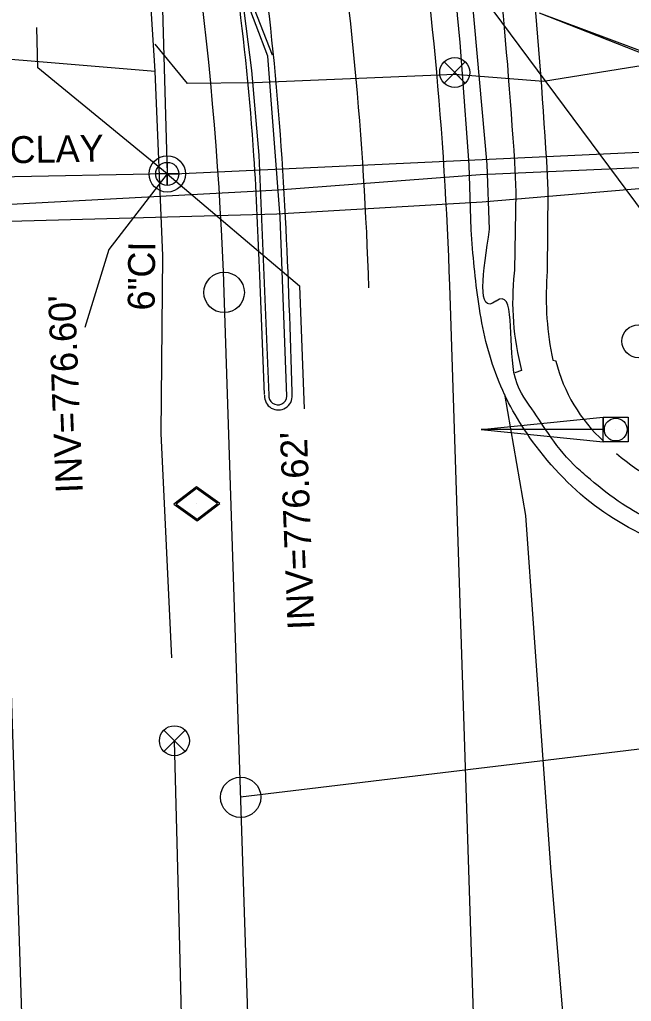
# Model space of a CAD drawing. Extents: x 1627482 to 1629573, y 760826 to 766301.
# Drawn here: x 1628458.5 to 1628549.3, y 761670.2 to 761816 of the extents above; entities that cross this region are included whole.
import ezdxf

# ---------------------------------------------------------------- set-up
doc = ezdxf.new("R2010")
doc.units = 0
for name, color, linetype in [('Exist Horizontal Alignment', 7, 'Continuous'), ('Exist Horizontal Alignment Point', 7, 'Continuous'), ('Exist Other Culture Fence Line', 7, 'Continuous'), ('Exist Right of Way Line', 7, 'Continuous'), ('Exist Roads Curbs', 7, 'Continuous'), ('Exist Roads EOP', 7, 'Continuous'), ('Exist Roads EOP Other', 7, 'Continuous'), ('Exist Roads EOT', 7, 'Continuous'), ('Exist Structure Minor Pipes RCP 18 Inch', 7, 'Continuous'), ('Exist Utilities Gas UG Line SUE LOS B', 7, 'Continuous'), ('Exist Utilities Gas Valve CELL', 7, 'Continuous'), ('Exist Utilities Other Pole Metal with Mast Arm CELL', 7, 'Continuous'), ('Exist Utilities Power Pole CELL', 7, 'Continuous'), ('Exist Utilities Sanitary Sewer Manhole CELL', 7, 'Continuous'), ('Exist Utilities Sanitary Sewer Manhole Leader', 7, 'Continuous'), ('Exist Utilities Sanitary Sewer UG Line', 7, 'Continuous'), ('Exist Utilities Sanitary Sewer UG Line Invert Elevation', 7, 'Continuous'), ('Exist Utilities Sanitary Sewer UG Line Leader', 7, 'Continuous'), ('Exist Utilities Sanitary Sewer UG Line Text', 7, 'Continuous'), ('Exist Utilities Water UG Line SUE', 7, 'Continuous'), ('Exist Utilities Water UG Line SUE LOS B', 7, 'Continuous'), ('Exist Utilities Water UG Line SUE Text', 7, 'Continuous'), ('Exist Utilities Water Valve CELL', 7, 'Continuous')]:
    doc.layers.add(name, color=color, linetype=linetype)

# ---------------------------------------------------------------- blocks, each defined once
blk = doc.blocks.new('EXIST UTILITIES WATER VALVE')
at = {"layer": 'Exist Utilities Water Valve CELL'}
blk.add_lwpolyline([(0.03150000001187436, 0.03150000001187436), (-0.031499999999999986, -0.03149999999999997), (0, 1.4210854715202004e-17), (0.03150000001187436, -0.03150000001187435), (-0.031499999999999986, 0.03150000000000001)], dxfattribs=at)
blk.add_circle((0, 0), 0.044547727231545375, dxfattribs=at)
blk = doc.blocks.new('EXIST UTILITIES GAS VALVE')
at = {"layer": 'Exist Utilities Gas Valve CELL'}
blk.add_line((0, 0), (0, 0), dxfattribs=at)
blk.add_lwpolyline([(0, 0.06825), (-0.05075, 0), (0, -0.06825), (0.05075, 0), (0, 0.06825)], dxfattribs=at)
blk.add_lwpolyline([(0.04576534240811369, 7.27595761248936e-18), (7.27595761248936e-18, 0.06154649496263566), (-0.04576534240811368, 0), (-7.27595761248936e-18, -0.06154649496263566)], close=True, dxfattribs=at)

msp = doc.modelspace()

# ---------------------------------------------------------------- linework, layer by layer
at = {"layer": 'Exist Horizontal Alignment'}
for p, q in [((1628498.6647146, 761475.6274153), (1628488.856999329, 761775.4670536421)), ((1628626.1058687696, 761716.7643783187), (1628491.3084665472, 761700.5212559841))]:
    msp.add_line(p, q, dxfattribs=at)
msp.add_arc((1627989.1242687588, 761759.1208615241), 500, 1.8734694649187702, 13.294655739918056, dxfattribs=at)
at = {"layer": 'Exist Horizontal Alignment Point'}
for centre in [(1628488.856999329, 761775.4670536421), (1628491.3084665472, 761700.5212559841)]:
    msp.add_circle(centre, 3, dxfattribs=at)
at = {"layer": 'Exist Other Culture Fence Line'}
msp.add_lwpolyline([(1629023.0696787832, 761658.0081255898), (1628929.497, 761723.8569999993), (1628897.894, 761738.8069999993), (1628861.8800000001, 761754.8679999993), (1628824.045, 761767.8569999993), (1628781.593, 761778.1989999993), (1628741.5960000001, 761784.8469999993), (1628702.129, 761788.6019999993), (1628662.165, 761788.6189999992), (1628626.173, 761786.1319999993), (1628617.683, 761785.6939999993), (1628593.545, 761794.1689999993), (1628535.6424837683, 761816.9022530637)], dxfattribs=at)
at = {"layer": 'Exist Right of Way Line'}
msp.add_line((1628617.731430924, 761786.2616357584), (1628535.6424837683, 761816.9022530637), dxfattribs=at)
at = {"layer": 'Exist Roads Curbs'}
for p, q in [((1628527.894, 761794.4743), (1628525.279, 761823.6529)), ((1628528.2550000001, 761784.8776), (1628527.894, 761794.4743)), ((1628538.083, 761765.3112000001), (1628538.099, 761765.263)), ((1628545.188, 761753.3518), (1628545.27, 761753.2674)), ((1628547.0790000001, 761751.5445), (1628547.0860000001, 761751.5432))]:
    msp.add_line(p, q, dxfattribs=at)
for centre, major_axis, ratio, start_param, end_param in [((1628561.380740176, 761771.0624674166), (6.980355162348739, -22.97217452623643), 0.9993276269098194, 4.661558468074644, 5.247238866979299), ((1628571.504853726, 761780.4198696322), (-6.690798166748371, -37.221658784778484), 0.9998936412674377, 5.759046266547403, 6.144520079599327)]:
    msp.add_ellipse(centre, major_axis=major_axis, ratio=ratio, start_param=start_param, end_param=end_param, dxfattribs=at)
msp.add_spline([(1628585.152, 761739.0867), (1628570.641, 761737.1304), (1628557.995, 761739.2484000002), (1628552.564, 761741.491), (1628547.941, 761744.0812), (1628543.216, 761747.6779), (1628541.249, 761749.403), (1628537.348, 761753.9899000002), (1628534.545, 761758.167), (1628531.877, 761763.5616), (1628529.214, 761774.1799), (1628529.186, 761774.1592000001), (1628528.2550000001, 761784.8776)], degree=3, dxfattribs=at)
at = {"layer": 'Exist Roads EOP'}
for p, q in [((1628525.506, 761784.7439), (1628525.209, 761794.4216)), ((1628494.1057751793, 761777.9985160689), (1628494.8097751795, 761760.3158160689)), ((1628494.8497751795, 761760.191516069), (1628494.8427751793, 761760.175716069)), ((1628498.9537751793, 761760.228416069), (1628498.9557751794, 761760.680616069))]:
    msp.add_line(p, q, dxfattribs=at)
msp.add_lwpolyline([(1628530.4510000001, 761760.356), (1628533.594, 761742.3427), (1628537.289, 761690.1147), (1628544.074, 761608.4722)], dxfattribs=at)
msp.add_ellipse((1628496.8998150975, 761760.0814345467), major_axis=(-1.7938323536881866, -1.0112468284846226), ratio=0.999936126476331, start_param=5.724027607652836, end_param=8.982864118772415, dxfattribs=at)
for points in [[(1628525.209, 761794.4216), (1628522.494, 761826.6554000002), (1628518.754, 761852.4106), (1628512.073, 761884.7975), (1628510.4540000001, 761891.1852)], [(1628486.9527751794, 761846.9901160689), (1628490.7297751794, 761820.9545160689), (1628493.2367751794, 761795.7535160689), (1628494.1057751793, 761777.9985160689)], [(1628498.9557751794, 761760.680616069), (1628497.9747751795, 761786.578216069), (1628495.7687751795, 761814.684716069), (1628491.9487751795, 761843.379716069)], [(1628596.338, 761742.2935), (1628592.156, 761739.5854), (1628588.985, 761737.9406000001), (1628586.057, 761736.7743), (1628586, 761736.7885), (1628570.546, 761734.5267), (1628556.804, 761736.9975), (1628544.524, 761743.3343), (1628534.641, 761753.3522), (1628529.413, 761762.7791), (1628526.636, 761773.7619000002), (1628525.506, 761784.7439)]]:
    msp.add_spline(points, degree=3, dxfattribs=at)
at = {"layer": 'Exist Roads EOP Other'}
for p, q in [((1628491.2777751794, 761821.1435160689), (1628492.9017751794, 761808.4243160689)), ((1628497.1837751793, 761786.625616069), (1628495.3367751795, 761810.539516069)), ((1628492.9017751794, 761808.4243160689), (1628494.0197751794, 761795.834416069)), ((1628494.0197751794, 761795.834416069), (1628495.5167751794, 761760.219116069)), ((1628536.68, 761795.0129), (1628536.905, 761790.5969)), ((1628531.965, 761794.7561), (1628532.151, 761790.3811)), ((1628536.905, 761790.5969), (1628536.793, 761778.5543)), ((1628532.151, 761790.3811), (1628531.941, 761778.7919)), ((1628498.1737751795, 761760.0692160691), (1628497.1837751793, 761786.625616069)), ((1628531.941, 761778.7919), (1628531.906, 761778.3458)), ((1628536.793, 761778.5543), (1628536.7619350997, 761777.863377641)), ((1628537.6551311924, 761765.4001565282), (1628538.083, 761765.3112000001)), ((1628533.009, 761763.8907000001), (1628531.99, 761763.5486000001)), ((1628495.5267751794, 761760.312416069), (1628495.5017751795, 761760.306516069))]:
    msp.add_line(p, q, dxfattribs=at)
for points in [[(1628495.3367751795, 761810.539516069), (1628491.8587751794, 761819.675116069), (1628491.3877751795, 761823.221216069), (1628492.4077751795, 761833.2204160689), (1628491.1287751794, 761843.214916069), (1628483.6917751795, 761880.4234160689), (1628482.8557751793, 761883.357916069), (1628470.2677751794, 761922.0964160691), (1628460.6667751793, 761951.578216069), (1628455.9276791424, 761960.1009013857), (1628454.8791133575, 761963.2857869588), (1628453.5017751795, 761973.2565160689), (1628451.0107751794, 761980.7920160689), (1628450.3687751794, 761990.7628160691)], [(1628496.0297751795, 761810.689616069), (1628492.4557751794, 761819.820716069), (1628491.9957751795, 761823.2489160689), (1628493.1357751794, 761833.0263160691)]]:
    msp.add_lwpolyline(points, dxfattribs=at)
for centre, major_axis, ratio, start_param, end_param in [((1628568.7010310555, 761773.7163582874), (5.414968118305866, -37.88976591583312), 0.9667061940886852, 4.453772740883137, 4.83489725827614), ((1628580.6033608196, 761774.7367494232), (-35.947935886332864, 25.292528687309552), 0.9998835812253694, 0.5419850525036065, 0.8272489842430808), ((1628496.8312352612, 761760.1141763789), (-1.2973951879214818, 0.34818570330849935), 0.999823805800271, 0.11853721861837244, 3.3703497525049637)]:
    msp.add_ellipse(centre, major_axis=major_axis, ratio=ratio, start_param=start_param, end_param=end_param, dxfattribs=at)
for points in [[(1628515.982, 761916.5141), (1628523.831, 761885.7485), (1628529.718, 761856.1136), (1628534.358, 761824.3539), (1628536.68, 761795.0129)], [(1628511.321, 761915.2462), (1628518.976, 761884.8585), (1628524.888, 761855.2505), (1628529.522, 761823.7848000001), (1628531.965, 761794.7561)]]:
    msp.add_spline(points, degree=3, dxfattribs=at)
at = {"layer": 'Exist Roads EOT'}
for p, q in [((1628548.942201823, 760963.2770036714), (1628522.3391165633, 761776.5622104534)), ((1628473.6826442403, 761214.6711144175), (1628455.3749077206, 761774.3718199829))]:
    msp.add_line(p, q, dxfattribs=at)
for radius in [559, 547]:
    msp.add_arc((1627963.6378869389, 761758.2871666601), radius, 1.8734694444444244, 15.718508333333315, dxfattribs=at)
at = {"layer": 'Exist Structure Minor Pipes RCP 18 Inch'}
msp.add_line((1628523.799493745, 761823.9927989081), (1628586.2186644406, 761739.8734830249), dxfattribs=at)
at = {"layer": 'Exist Utilities Gas UG Line SUE LOS B'}
for points in [[(1628420.2900000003, 761787.7210000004), (1628447.9510000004, 761788.0670000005), (1628496.8830000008, 761790.7160000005), (1628526.8670000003, 761792.9540000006), (1628563.9840000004, 761794.5860000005), (1628591.6730000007, 761794.7190000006), (1628689.3340000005, 761799.0300000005), (1628838.0560000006, 761773.7130000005)], [(1628420.4330000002, 761784.5700000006), (1628448.0270000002, 761785.7770000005), (1628496.6620000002, 761787.1120000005), (1628527.132, 761788.9060000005), (1628563.7850000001, 761792.0470000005), (1628592.1130000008, 761793.0740000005), (1628653.308, 761786.6860000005), (1628679.4980000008, 761787.9360000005), (1628788.3600000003, 761777.6870000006), (1628820.9610000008, 761770.5400000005)]]:
    msp.add_lwpolyline(points, dxfattribs=at)
at = {"layer": 'Exist Utilities Other Pole Metal with Mast Arm CELL'}
msp.add_line((1628546.977, 761755.1075), (1628546.977, 761755.1075), dxfattribs=at)
msp.add_lwpolyline([(1628527.010254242, 761755.1165301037), (1628545.122754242, 761756.9540301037), (1628545.122754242, 761755.1165301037), (1628527.010254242, 761755.1165301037), (1628545.122754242, 761753.2665301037)], dxfattribs=at)
msp.add_lwpolyline([(1628548.822754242, 761753.2665301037), (1628545.122754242, 761753.2665301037), (1628545.122754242, 761756.9540301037), (1628548.822754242, 761756.9540301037)], close=True, dxfattribs=at)
msp.add_circle((1628546.977, 761755.1075), 1.6899056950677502, dxfattribs=at)
at = {"layer": 'Exist Utilities Power Pole CELL'}
msp.add_circle((1628550.351, 761768.2237), 2.450127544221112, dxfattribs=at)
at = {"layer": 'Exist Utilities Sanitary Sewer Manhole CELL'}
msp.add_lwpolyline([(1628480.421, 761794.7745), (1628480.421, 761791.3495), (1628480.421, 761793.062), (1628482.1335, 761793.062), (1628478.7085, 761793.062)], dxfattribs=at)
for radius in [2.694426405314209, 1.7124999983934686]:
    msp.add_circle((1628480.421, 761793.062), radius, dxfattribs=at)
at = {"layer": 'Exist Utilities Sanitary Sewer Manhole Leader'}
msp.add_lwpolyline([(1628480.421, 761793.062), (1628461.1987409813, 761808.8114686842), (1628461.0725364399, 761814.8101412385)], dxfattribs=at)
at = {"layer": 'Exist Utilities Sanitary Sewer UG Line'}
for p, q in [((1628470.827, 762121.0989), (1628480.421, 761793.062)), ((1628481.532972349, 761793.0803672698), (1628714.4636314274, 761803.9316177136)), ((1628480.421, 761793.062), (1628440.34, 761792.319))]:
    msp.add_line(p, q, dxfattribs=at)
at = {"layer": 'Exist Utilities Sanitary Sewer UG Line Leader'}
for points in [[(1628480.421, 761793.062), (1628471.7533322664, 761781.8244392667), (1628468.2009007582, 761770.237411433)], [(1628480.421, 761793.062), (1628500.0248519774, 761776.4526761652), (1628500.7459553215, 761758.1660014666)]]:
    msp.add_lwpolyline(points, dxfattribs=at)
at = {"layer": 'Exist Utilities Water UG Line SUE'}
for points in [[(1628481.081217, 761721.2077029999), (1628479.503486, 761754.5401579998), (1628479.764953, 761780.895705), (1628478.6204660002, 761808.3103070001), (1628475.7084120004, 761853.980013), (1628474.686685, 761890.7555949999), (1628473.2966330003, 761930.329586), (1628471.6428690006, 761967.6760380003)], [(1628422.4070385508, 761803.768470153), (1628423.6851773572, 761804.3185298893), (1628424.4102561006, 761810.4251930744), (1628426.5464880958, 761812.1263778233), (1628438.7688154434, 761811.6423252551), (1628478.6204660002, 761808.3103070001)], [(1628396.3124069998, 761583.159534), (1628408.0384781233, 761595.8668919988), (1628420.1947983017, 761607.8531937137), (1628428.4496947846, 761619.9135034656), (1628440.5850126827, 761632.0018162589), (1628454.1714881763, 761646.359375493), (1628483.053306, 761646.002311), (1628482.13426, 761684.2901760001), (1628481.4787220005, 761708.913347)]]:
    msp.add_lwpolyline(points, dxfattribs=at)
at = {"layer": 'Exist Utilities Water UG Line SUE LOS B'}
msp.add_lwpolyline([(1628580.2640000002, 761811.1020000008), (1628577.8130000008, 761810.0950000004), (1628560.983, 761810.0980000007), (1628550.1210000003, 761808.9900000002), (1628536.279, 761806.7980000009), (1628523.1170000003, 761807.8220000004), (1628493.364, 761806.5890000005), (1628483.4090000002, 761806.5000000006), (1628478.6290000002, 761812.3300000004)], dxfattribs=at)
at = {"layer": 'Exist Utilities Water Valve CELL'}
msp.add_lwpolyline([(1628524.6520000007, 761809.6890000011), (1628521.5020000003, 761806.5390000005), (1628523.0770000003, 761808.1140000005), (1628524.6520000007, 761806.5389999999), (1628521.5020000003, 761809.6890000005)], dxfattribs=at)
msp.add_circle((1628523.0770000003, 761808.1140000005), 2.227386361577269, dxfattribs=at)

# ---------------------------------------------------------------- block references
at = {"layer": 'Exist Utilities Gas Valve CELL', "xscale": 50.00000000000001, "yscale": 50, "rotation": 91.06538519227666}
msp.add_blockref('EXIST UTILITIES GAS VALVE', (1628484.8058150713, 761744.0939894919), dxfattribs=at)
at = {"layer": 'Exist Utilities Water Valve CELL', "xscale": 50, "yscale": 50}
msp.add_blockref('EXIST UTILITIES WATER VALVE', (1628481.4787220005, 761708.913347), dxfattribs=at)

# ---------------------------------------------------------------- texts
at = {"layer": 'Exist Utilities Sanitary Sewer UG Line Invert Elevation'}
for s, p in [("INV=776.60'", (1628467.889259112, 761745.7466796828)), ("INV=776.62'", (1628502.291482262, 761725.457168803))]:
    msp.add_text(s, height=4.000000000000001, rotation=92.25818983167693, dxfattribs=at).set_placement(p)
at = {"layer": 'Exist Utilities Sanitary Sewer UG Line Text'}
msp.add_text('8" CLAY', height=3.9999999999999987, rotation=1.061996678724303, dxfattribs=at).set_placement((1628450.687184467, 761794.5111541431))
at = {"layer": 'Exist Utilities Water UG Line SUE Text'}
msp.add_text('6"CI', height=4, rotation=89.43160109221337, dxfattribs=at).set_placement((1628478.5391823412, 761772.7697889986))

doc.saveas('drawing.dxf')
